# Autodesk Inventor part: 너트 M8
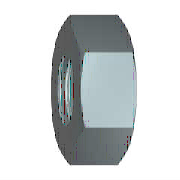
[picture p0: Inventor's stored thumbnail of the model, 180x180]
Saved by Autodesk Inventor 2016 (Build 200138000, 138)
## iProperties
Created: 2012-02
Part Number: 너트 M8
Material: 강철, 연강
Description: 6각 너트 및 6각 가는 너트
Document SubType Name: Modeling
Standard: KS B 1012
Designer: mduedu
Standards Organization: KS
Language: ko-KR
Size Designation: M 8
Categories: <MemberInstance><Categories><Category DisplayName="조임쇠" InternalName="e4da775c-781d-43d5-af7c-5136215cf5a6" Mnemonic="FSTN"><Category DisplayName="너트" InternalN
Density: 1 g/cm^3
Appearance: 강철
IsCustomPart: 1
Author: mduedu
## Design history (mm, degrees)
sketch "스케치1"
  geometry: L1 (-7.506, 0)-(-3.753, 6.5); L2 (-3.753, 6.5)-(3.753, 6.5); L3 (3.753, 6.5)-(7.506, 0); L4 (7.506, 0)-(3.753, -6.5); L5 (3.753, -6.5)-(-3.753, -6.5); L6 (-3.753, -6.5)-(-7.506, 0); 2 further points
  constraints: 12 end point, 1 coincident, 1 horizontal, 11 other
  dimensions: "d0" = 15.01111 distance of L3.end L1.start (= 1.1547 x SW)
extrude "본체" new body sketch "스케치1" distance "d1" = 5 (= KOH); taper "d2" = 0 deg
sketch "스케치2"
  geometry: L1 (0, 3.753)-(0, 7.506) reference; L2 (0, 7.506)-(5, 7.506) reference; L3 (5, 3.753)-(5, 7.506) reference; L4 (-1, 0)-(6, 0) reference; L5 (0.581, 7.506)-(0, 6.5); L6 (4.419, 7.506)-(5, 6.5)
  constraints: 4 end point, 4 point on line
  dimensions: "d3" = 30 deg angle of L1 L5 (= ANG1); "d4" = 30 deg angle of L3 L6 (= ANG2); "d5" = 13 diameter of L5.end L4 (= SW0); "d6" = 13 diameter of L6.end L4 (= SW01)
revolve "모따기1" sketch "스케치2" stored, may be unused: angle "d7" = 90 deg
sketch "스케치3"
  geometry: A1 r 6.5 centre (0, 0) between (-3.25, -5.629) and (3.25, -5.629) reference; 1 further point
  constraints: 1 coincident
hole "스레드" sketch "스케치3" at (0, 0) diameter "d25" = 6.647; stored, may be unused: countersink angle "d29" = 82 deg, drill point angle "d31" = 118 deg; dims "d26" = 6, "d27" = 4, "d28" = 2, "d30" = 8
workaxis "Work Axis1"
workplane "Work Plane1"
body "Solid1"
chamfer "모따기2" distance "d8" = 0.67658 (= -0.5 x GD1 + 0.5 x NND); stored, may be unused: angle "d9" = 30 deg, second distance "d40" = 0.67658 (= -0.5 x GD1 + 0.5 x NND)
chamfer "모따기3" distance "d10" = 0.67658 (= -0.5 x GD1 + 0.5 x NND); stored, may be unused: angle "d11" = 30 deg, second distance "d41" = 0.67658 (= -0.5 x GD1 + 0.5 x NND)
other parameters: "ANG1" = 30 deg [user parameter; used in 1 equation term], "ANG2" = 30 deg [user parameter; used in 1 equation term], "NND" = 8 [user parameter; used in 4 equation terms], "KOH" = 5 [user parameter; used in 1 equation term], "SW" = 13 [user parameter; used in 4 equation terms], "SW0" = 13 (= SW) [user parameter; used in 1 equation term], "SW01" = 13 (= SW) [user parameter; used in 1 equation term], "GD1" = 6.64684 (computed from THREADDIA, PTC, TOA) [user parameter; used in 4 equation terms], "d13" = 0, "d14" = 0, "d39" = 0, "d42" = 0, "GUL" = 0.67658 (= 0.541266 x PTC) [user parameter], "TPU" = 8 (computed from PTC) [user parameter], "THREADDIA" = 8 [user parameter; used in 1 equation term], "TOA" = 30 deg [user parameter; used in 1 equation term], "PTC" = 1.25 [user parameter; used in 4 equation terms], "E0" = 15.015 (= 1.155 x SW) [user parameter], "GAL" = 0.67658 (= 0.541266 x PTC) [user parameter]
